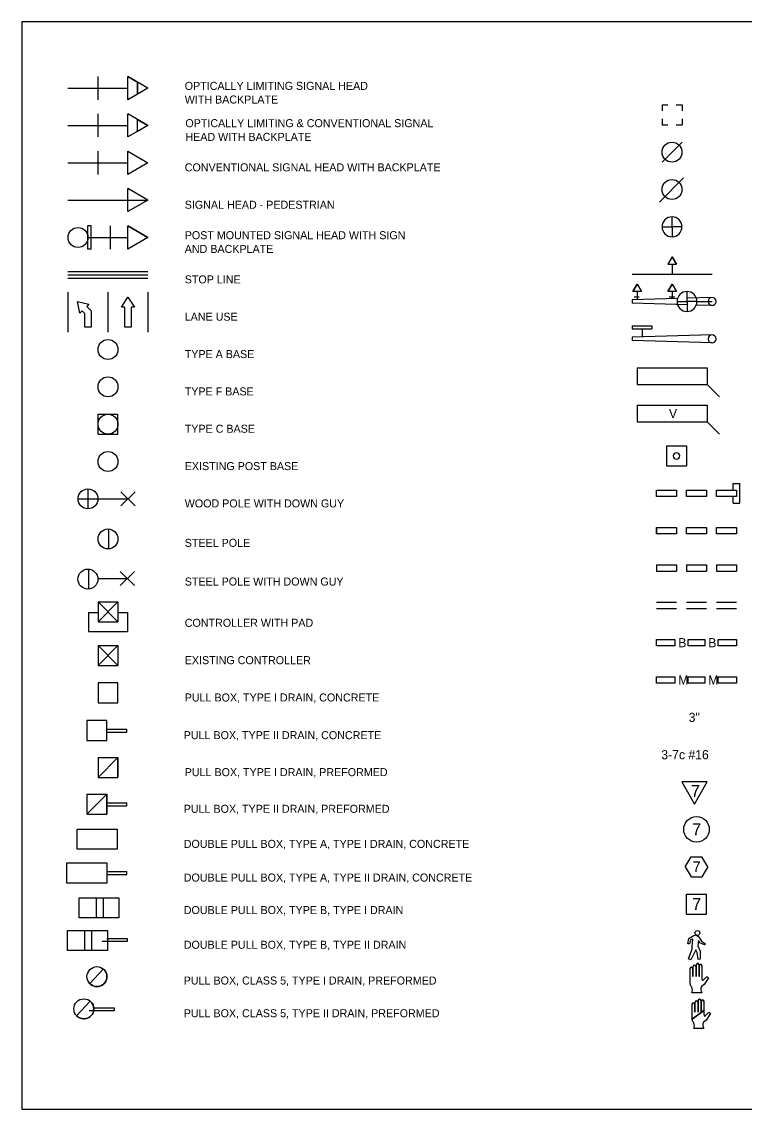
# Model space of a CAD drawing. Extents: x -439.1 to -407.9, y -458.1 to -437.7.
# Drawn here: x -439.11 to -425.57, y -458.05 to -437.68 of the extents above; entities that cross this region are included whole.
import ezdxf

# ---------------------------------------------------------------- set-up
doc = ezdxf.new("R2010")
doc.units = 0
doc.layers.add('Draft_Named_Boundary', color=7, linetype='Continuous')
doc.layers.add('Level 4', color=7, linetype='Continuous')

msp = doc.modelspace()

# ---------------------------------------------------------------- linework, layer by layer
at = {"layer": 'Draft_Named_Boundary'}
msp.add_lwpolyline([(-439.109, -458.051), (-407.859, -458.051), (-407.859, -437.676), (-439.109, -437.676)], close=True, dxfattribs=at)
at = {"layer": 'Level 4'}
for p, q in [((-437.68, -439.136), (-437.68, -438.703)), ((-437.119, -439.136), (-437.119, -438.703)), ((-436.744, -438.919), (-437.119, -438.703)), ((-436.938, -439.032), (-436.938, -438.807)), ((-438.243, -438.919), (-437.119, -438.919)), ((-436.744, -438.919), (-437.119, -439.136)), ((-427.112, -439.232), (-427.001, -439.232)), ((-427.112, -439.232), (-427.112, -439.343)), ((-426.848, -439.232), (-426.737, -439.232)), ((-426.737, -439.232), (-426.737, -439.343)), ((-437.68, -439.835), (-437.68, -439.403)), ((-436.744, -439.619), (-437.119, -439.403)), ((-437.119, -439.835), (-437.119, -439.403)), ((-438.243, -439.619), (-437.119, -439.619)), ((-436.744, -439.619), (-437.119, -439.835)), ((-436.938, -439.732), (-436.938, -439.506)), ((-427.112, -439.496), (-427.112, -439.607)), ((-427.112, -439.607), (-427.001, -439.607)), ((-426.848, -439.607), (-426.737, -439.607)), ((-426.737, -439.496), (-426.737, -439.607)), ((-426.737, -439.932), (-427.112, -440.307)), ((-437.68, -440.535), (-437.68, -440.102)), ((-437.119, -440.102), (-436.744, -440.319)), ((-437.119, -440.535), (-437.119, -440.102)), ((-438.243, -440.319), (-437.119, -440.319)), ((-436.744, -440.319), (-437.119, -440.535)), ((-426.708, -440.602), (-427.159, -441.053)), ((-436.744, -441.018), (-437.119, -440.802)), ((-437.119, -441.234), (-437.119, -440.802)), ((-438.243, -441.018), (-436.744, -441.018)), ((-436.744, -441.018), (-437.119, -441.234)), ((-437.868, -441.934), (-437.868, -441.501)), ((-437.808, -441.501), (-437.868, -441.501)), ((-437.808, -441.934), (-437.808, -441.501)), ((-437.444, -441.934), (-437.444, -441.501)), ((-436.744, -441.718), (-437.119, -441.501)), ((-437.119, -441.934), (-437.119, -441.501)), ((-427.112, -441.518), (-426.925, -441.518)), ((-426.925, -441.518), (-426.925, -441.331)), ((-426.737, -441.518), (-426.925, -441.518)), ((-426.925, -441.518), (-426.925, -441.706)), ((-426.737, -441.518), (-426.737, -441.518)), ((-437.868, -441.718), (-437.119, -441.718)), ((-436.744, -441.718), (-437.119, -441.934)), ((-437.808, -441.934), (-437.868, -441.934)), ((-426.925, -442.078), (-427.006, -442.218)), ((-426.925, -442.078), (-426.844, -442.218)), ((-427.006, -442.218), (-426.844, -442.218)), ((-426.925, -442.218), (-426.925, -442.405)), ((-438.243, -442.357), (-436.744, -442.357)), ((-438.243, -442.417), (-436.744, -442.417)), ((-438.243, -442.477), (-436.744, -442.477)), ((-427.674, -442.405), (-426.175, -442.405)), ((-438.243, -442.742), (-438.243, -443.492)), ((-437.493, -442.742), (-437.493, -443.492)), ((-436.744, -442.742), (-436.744, -443.492)), ((-427.581, -442.59), (-427.662, -442.73)), ((-427.581, -442.59), (-427.499, -442.73)), ((-427.581, -442.73), (-427.581, -442.884)), ((-426.925, -442.59), (-427.006, -442.73)), ((-426.925, -442.59), (-426.844, -442.73)), ((-426.925, -442.73), (-426.925, -442.865)), ((-426.643, -442.917), (-426.643, -442.73)), ((-438.019, -443.135), (-438.067, -442.918)), ((-438.067, -442.918), (-437.849, -442.965)), ((-437.238, -443.023), (-437.119, -442.836)), ((-437.128, -442.85), (-437.116, -442.839)), ((-437.119, -442.836), (-436.998, -443.023)), ((-426.823, -442.862), (-427.674, -442.887)), ((-427.674, -442.887), (-427.674, -442.948)), ((-426.643, -442.978), (-427.674, -442.948)), ((-427.633, -442.827), (-427.538, -442.827)), ((-426.976, -442.827), (-426.872, -442.827)), ((-426.831, -442.917), (-426.643, -442.917)), ((-426.456, -442.917), (-426.644, -442.917)), ((-426.644, -442.917), (-426.644, -443.105)), ((-426.175, -442.842), (-426.643, -442.857)), ((-426.456, -442.917), (-426.175, -442.917)), ((-437.977, -443.093), (-438.019, -443.135)), ((-437.928, -443.142), (-437.977, -443.093)), ((-437.928, -443.398), (-437.928, -443.142)), ((-437.849, -442.965), (-437.892, -443.008)), ((-437.892, -443.008), (-437.808, -443.092)), ((-437.808, -443.092), (-437.808, -443.398)), ((-437.179, -443.023), (-437.238, -443.023)), ((-437.179, -443.398), (-437.179, -443.023)), ((-436.998, -443.023), (-437.059, -443.023)), ((-437.059, -443.023), (-437.059, -443.398)), ((-426.175, -442.992), (-426.469, -442.984)), ((-437.808, -443.398), (-437.928, -443.398)), ((-437.059, -443.398), (-437.179, -443.398)), ((-427.674, -443.37), (-427.3, -443.37)), ((-427.674, -443.37), (-427.674, -443.429)), ((-427.674, -443.429), (-427.3, -443.429)), ((-426.175, -443.542), (-427.674, -443.587)), ((-427.487, -443.429), (-427.487, -443.581)), ((-427.3, -443.37), (-427.3, -443.429)), ((-427.674, -443.587), (-427.674, -443.647)), ((-426.175, -443.692), (-427.674, -443.647)), ((-427.581, -444.163), (-427.581, -444.47)), ((-427.581, -444.163), (-426.269, -444.163)), ((-426.269, -444.163), (-426.269, -444.47)), ((-427.581, -444.47), (-426.269, -444.47)), ((-426.269, -444.47), (-426.033, -444.705)), ((-427.581, -444.862), (-427.581, -445.169)), ((-427.581, -444.862), (-426.269, -444.862)), ((-426.269, -444.862), (-426.269, -445.169)), ((-437.68, -445.028), (-437.306, -445.028)), ((-437.68, -445.403), (-437.68, -445.028)), ((-437.306, -445.403), (-437.306, -445.028)), ((-427.581, -445.169), (-426.269, -445.169)), ((-426.269, -445.169), (-426.033, -445.405)), ((-437.68, -445.403), (-437.306, -445.403)), ((-427.028, -445.624), (-427.028, -445.998)), ((-427.028, -445.624), (-426.654, -445.624)), ((-426.654, -445.624), (-426.654, -445.998)), ((-427.028, -445.998), (-426.654, -445.998)), ((-425.777, -446.324), (-425.657, -446.324)), ((-425.777, -446.451), (-425.777, -446.324)), ((-425.657, -446.698), (-425.657, -446.324)), ((-438.055, -446.614), (-437.119, -446.614)), ((-437.868, -446.427), (-437.868, -446.802)), ((-436.986, -446.482), (-437.251, -446.747)), ((-437.251, -446.482), (-436.986, -446.747)), ((-427.216, -446.571), (-427.216, -446.451)), ((-427.216, -446.451), (-426.841, -446.451)), ((-426.841, -446.571), (-427.216, -446.571)), ((-426.841, -446.451), (-426.841, -446.571)), ((-426.654, -446.571), (-426.654, -446.451)), ((-426.654, -446.451), (-426.278, -446.451)), ((-426.278, -446.571), (-426.654, -446.571)), ((-426.278, -446.451), (-426.278, -446.571)), ((-426.091, -446.571), (-426.091, -446.451)), ((-426.091, -446.451), (-425.717, -446.451)), ((-425.717, -446.571), (-426.091, -446.571)), ((-425.777, -446.698), (-425.777, -446.571)), ((-425.717, -446.451), (-425.717, -446.571)), ((-425.777, -446.698), (-425.657, -446.698)), ((-437.481, -447.179), (-437.481, -447.553)), ((-427.216, -447.15), (-427.216, -447.271)), ((-427.216, -447.271), (-427.216, -447.15)), ((-427.216, -447.271), (-427.216, -447.15)), ((-427.216, -447.15), (-426.841, -447.15)), ((-426.841, -447.15), (-426.841, -447.271)), ((-426.654, -447.271), (-426.654, -447.15)), ((-426.654, -447.15), (-426.278, -447.15)), ((-426.278, -447.15), (-426.278, -447.271)), ((-426.091, -447.271), (-426.091, -447.15)), ((-426.091, -447.15), (-425.717, -447.15)), ((-425.717, -447.15), (-425.717, -447.271)), ((-426.841, -447.271), (-427.216, -447.271)), ((-426.278, -447.271), (-426.654, -447.271)), ((-425.717, -447.271), (-426.091, -447.271)), ((-437.856, -447.931), (-437.856, -448.305)), ((-436.997, -447.976), (-437.262, -448.241)), ((-437.262, -447.976), (-436.997, -448.241)), ((-427.216, -447.85), (-427.216, -447.97)), ((-427.216, -447.85), (-426.841, -447.85)), ((-427.216, -447.97), (-426.841, -447.97)), ((-426.841, -447.85), (-426.841, -447.97)), ((-426.654, -447.85), (-426.654, -447.97)), ((-426.654, -447.85), (-426.278, -447.85)), ((-426.654, -447.97), (-426.278, -447.97)), ((-426.278, -447.85), (-426.278, -447.97)), ((-426.091, -447.85), (-426.091, -447.97)), ((-426.091, -447.85), (-425.717, -447.85)), ((-426.091, -447.97), (-425.717, -447.97)), ((-425.717, -447.85), (-425.717, -447.97)), ((-437.682, -448.108), (-437.13, -448.108)), ((-437.68, -448.546), (-437.68, -448.92)), ((-437.68, -448.546), (-437.306, -448.546)), ((-437.68, -448.546), (-437.306, -448.92)), ((-437.306, -448.546), (-437.68, -448.92)), ((-437.306, -448.546), (-437.306, -448.92)), ((-427.216, -448.549), (-426.841, -448.549)), ((-426.654, -448.549), (-426.278, -448.549)), ((-426.091, -448.549), (-425.717, -448.549)), ((-437.859, -448.742), (-437.859, -449.099)), ((-437.859, -448.742), (-437.68, -448.742)), ((-437.306, -448.742), (-437.127, -448.742)), ((-437.127, -448.742), (-437.127, -449.099)), ((-427.216, -448.669), (-426.841, -448.669)), ((-426.654, -448.669), (-426.278, -448.669)), ((-426.091, -448.669), (-425.717, -448.669)), ((-437.68, -448.92), (-437.306, -448.92)), ((-437.859, -449.099), (-437.127, -449.099)), ((-427.216, -449.369), (-427.216, -449.25)), ((-427.216, -449.25), (-426.871, -449.25)), ((-426.871, -449.25), (-426.871, -449.369)), ((-426.623, -449.369), (-426.623, -449.25)), ((-426.623, -449.25), (-426.309, -449.25)), ((-426.309, -449.25), (-426.309, -449.369)), ((-426.062, -449.369), (-426.062, -449.25)), ((-426.062, -449.25), (-425.717, -449.25)), ((-425.717, -449.25), (-425.717, -449.369)), ((-437.306, -449.364), (-437.68, -449.738)), ((-437.68, -449.364), (-437.306, -449.364)), ((-437.68, -449.364), (-437.306, -449.738)), ((-437.68, -449.364), (-437.68, -449.738)), ((-437.306, -449.364), (-437.306, -449.738)), ((-426.871, -449.369), (-427.216, -449.369)), ((-426.309, -449.369), (-426.623, -449.369)), ((-425.717, -449.369), (-426.062, -449.369)), ((-437.68, -449.738), (-437.306, -449.738)), ((-437.306, -450.063), (-437.68, -450.063)), ((-437.68, -450.063), (-437.68, -450.438)), ((-437.306, -450.438), (-437.306, -450.063)), ((-427.216, -450.068), (-427.216, -449.949)), ((-427.216, -449.949), (-426.871, -449.949)), ((-426.871, -450.068), (-427.216, -450.068)), ((-426.871, -449.949), (-426.871, -450.068)), ((-426.623, -450.068), (-426.623, -449.949)), ((-426.623, -449.949), (-426.309, -449.949)), ((-426.309, -450.068), (-426.623, -450.068)), ((-426.309, -449.949), (-426.309, -450.068)), ((-426.062, -450.068), (-426.062, -449.949)), ((-426.062, -449.949), (-425.717, -449.949)), ((-425.717, -450.068), (-426.062, -450.068)), ((-425.717, -449.949), (-425.717, -450.068)), ((-437.68, -450.438), (-437.306, -450.438)), ((-437.512, -450.769), (-437.887, -450.769)), ((-437.887, -450.769), (-437.887, -451.144)), ((-437.512, -451.144), (-437.512, -450.769)), ((-437.512, -450.927), (-437.137, -450.927)), ((-437.512, -450.986), (-437.137, -450.986)), ((-437.137, -450.986), (-437.137, -450.927)), ((-437.887, -451.144), (-437.512, -451.144)), ((-437.68, -451.463), (-437.68, -451.837)), ((-437.68, -451.463), (-437.306, -451.463)), ((-437.306, -451.463), (-437.68, -451.837)), ((-437.306, -451.463), (-437.306, -451.837)), ((-437.68, -451.837), (-437.306, -451.837)), ((-426.264, -451.919), (-426.743, -451.919)), ((-426.743, -451.919), (-426.504, -452.333)), ((-426.504, -452.333), (-426.264, -451.919)), ((-437.887, -452.149), (-437.887, -452.524)), ((-437.887, -452.149), (-437.512, -452.149)), ((-437.887, -452.524), (-437.512, -452.149)), ((-437.512, -452.149), (-437.512, -452.524)), ((-437.512, -452.307), (-437.137, -452.307)), ((-437.137, -452.367), (-437.137, -452.307)), ((-437.887, -452.524), (-437.512, -452.524)), ((-437.512, -452.367), (-437.137, -452.367)), ((-426.677, -453.507), (-426.569, -453.319)), ((-426.569, -453.319), (-426.364, -453.319)), ((-426.256, -453.507), (-426.364, -453.319)), ((-426.677, -453.507), (-426.569, -453.694)), ((-426.256, -453.507), (-426.364, -453.694)), ((-437.512, -453.595), (-437.137, -453.595)), ((-437.512, -453.655), (-437.137, -453.655)), ((-437.137, -453.655), (-437.137, -453.595)), ((-426.569, -453.694), (-426.364, -453.694)), ((-438.036, -454.092), (-437.287, -454.092)), ((-426.654, -454.019), (-426.278, -454.019)), ((-426.654, -454.394), (-426.654, -454.019)), ((-426.278, -454.394), (-426.278, -454.019)), ((-437.287, -454.467), (-438.036, -454.467)), ((-426.654, -454.394), (-426.278, -454.394)), ((-438.251, -454.7), (-437.502, -454.7)), ((-426.631, -454.95), (-426.612, -454.854)), ((-426.6, -454.952), (-426.631, -454.95)), ((-426.612, -454.854), (-426.526, -454.804)), ((-426.578, -454.874), (-426.6, -454.952)), ((-426.536, -454.862), (-426.578, -454.874)), ((-426.55, -455.001), (-426.536, -454.862)), ((-426.526, -454.804), (-426.49, -454.792)), ((-426.49, -454.792), (-426.481, -454.785)), ((-426.49, -454.792), (-426.49, -454.792)), ((-426.481, -454.785), (-426.465, -454.794)), ((-426.465, -454.794), (-426.451, -454.795)), ((-426.451, -454.795), (-426.444, -454.806)), ((-426.444, -454.806), (-426.421, -454.823)), ((-426.431, -454.891), (-426.44, -454.99)), ((-426.404, -454.93), (-426.431, -454.891)), ((-426.421, -454.823), (-426.375, -454.903)), ((-426.314, -454.972), (-426.404, -454.93)), ((-426.375, -454.903), (-426.299, -454.954)), ((-426.299, -454.954), (-426.314, -454.972)), ((-437.502, -455.075), (-438.251, -455.075)), ((-426.613, -455.235), (-426.545, -455.054)), ((-426.48, -455.064), (-426.572, -455.25)), ((-426.545, -455.054), (-426.55, -455.001)), ((-426.452, -455.117), (-426.48, -455.064)), ((-426.437, -455.244), (-426.452, -455.117)), ((-426.44, -454.99), (-426.399, -455.088)), ((-426.399, -455.088), (-426.396, -455.241)), ((-426.572, -455.25), (-426.613, -455.235)), ((-426.527, -455.551), (-426.527, -455.378)), ((-426.481, -455.378), (-426.481, -455.551)), ((-426.469, -455.551), (-426.469, -455.343)), ((-426.396, -455.241), (-426.437, -455.244)), ((-426.423, -455.343), (-426.423, -455.551)), ((-426.411, -455.551), (-426.411, -455.361)), ((-426.365, -455.361), (-426.365, -455.602)), ((-437.579, -455.423), (-437.836, -455.696)), ((-437.579, -455.423), (-437.836, -455.696)), ((-426.585, -455.705), (-426.585, -455.413)), ((-426.539, -455.413), (-426.539, -455.551)), ((-426.248, -455.583), (-426.24, -455.591)), ((-426.36, -455.626), (-426.358, -455.63)), ((-426.34, -455.633), (-426.297, -455.586)), ((-426.365, -455.868), (-426.556, -455.868)), ((-437.824, -456.027), (-438.081, -456.299)), ((-437.824, -456.027), (-438.081, -456.299)), ((-426.547, -456.374), (-426.547, -456.081)), ((-426.501, -456.081), (-426.501, -456.22)), ((-426.489, -456.22), (-426.489, -456.047)), ((-426.443, -456.047), (-426.443, -456.22)), ((-426.431, -456.22), (-426.431, -456.012)), ((-426.385, -456.012), (-426.385, -456.22)), ((-426.373, -456.22), (-426.373, -456.029)), ((-426.327, -456.029), (-426.327, -456.201)), ((-426.547, -456.363), (-426.327, -456.201)), ((-426.327, -456.201), (-426.327, -456.271)), ((-426.322, -456.295), (-426.32, -456.298)), ((-426.302, -456.302), (-426.259, -456.254)), ((-426.21, -456.252), (-426.202, -456.26)), ((-426.327, -456.537), (-426.518, -456.537))]:
    msp.add_line(p, q, dxfattribs=at)
for points in [[(-437.119, -438.703), (-436.938, -438.807), (-436.938, -439.032), (-437.119, -439.136)], [(-436.938, -439.506), (-436.744, -439.619), (-436.938, -439.732)], [(-436.744, -441.018), (-437.119, -441.234), (-437.119, -441.018)], [(-437.119, -441.501), (-436.744, -441.718), (-437.119, -441.934)], [(-426.925, -442.078), (-427.006, -442.218), (-426.844, -442.218)], [(-427.662, -442.73), (-427.581, -442.59), (-427.499, -442.73)], [(-427.006, -442.73), (-426.925, -442.59), (-426.844, -442.73)], [(-437.306, -451.463), (-437.68, -451.837), (-437.306, -451.837)], [(-437.512, -452.149), (-437.887, -452.524), (-437.512, -452.524)], [(-438.073, -452.805), (-437.324, -452.805), (-437.324, -453.181), (-438.073, -453.181)], [(-438.262, -453.437), (-437.512, -453.437), (-437.512, -453.812), (-438.262, -453.812)], [(-426.547, -456.363), (-426.547, -456.081), (-426.542, -456.065), (-426.532, -456.057), (-426.518, -456.057), (-426.508, -456.062), (-426.501, -456.081), (-426.501, -456.22), (-426.497, -456.225), (-426.493, -456.225), (-426.49, -456.225), (-426.49, -456.22), (-426.489, -456.22), (-426.489, -456.047), (-426.489, -456.047), (-426.483, -456.03), (-426.466, -456.02), (-426.451, -456.027), (-426.443, -456.047), (-426.443, -456.22), (-426.439, -456.225), (-426.435, -456.225), (-426.432, -456.225), (-426.431, -456.22), (-426.431, -456.012), (-426.431, -456.003), (-426.42, -455.99), (-426.407, -455.986), (-426.392, -455.992), (-426.385, -456.012), (-426.385, -456.22), (-426.385, -456.227), (-426.379, -456.227), (-426.374, -456.227), (-426.374, -456.218), (-426.373, -456.22), (-426.373, -456.029), (-426.367, -456.013), (-426.35, -456.003), (-426.336, -456.01), (-426.327, -456.029), (-426.327, -456.201)]]:
    msp.add_lwpolyline(points, close=True, dxfattribs=at)
for points in [[(-437.717, -454.467), (-438.036, -454.467), (-438.036, -454.092), (-437.717, -454.092)], [(-437.717, -454.092), (-437.717, -454.467)], [(-437.578, -454.467), (-437.578, -454.092)], [(-437.578, -454.092), (-437.287, -454.092), (-437.287, -454.467), (-437.578, -454.467)], [(-437.932, -455.075), (-438.251, -455.075), (-438.251, -454.7), (-437.932, -454.7)], [(-437.932, -454.7), (-437.932, -455.075)], [(-437.793, -455.075), (-437.793, -454.7)], [(-437.793, -454.7), (-437.502, -454.7), (-437.502, -455.075), (-437.793, -455.075)], [(-437.515, -454.849), (-437.136, -454.849), (-437.136, -454.906), (-437.604, -454.906)], [(-426.24, -455.591), (-426.325, -455.711), (-426.371, -455.753)], [(-437.758, -456.15), (-437.378, -456.15), (-437.378, -456.207), (-437.846, -456.207)], [(-426.202, -456.26), (-426.287, -456.379), (-426.333, -456.421)]]:
    msp.add_lwpolyline(points, dxfattribs=at)
for centre, radius in [((-426.925, -440.119), 0.187), ((-426.925, -440.819), 0.187), ((-438.055, -441.718), 0.187), ((-437.493, -443.816), 0.187), ((-437.493, -444.516), 0.187), ((-437.493, -445.216), 0.187), ((-437.493, -445.915), 0.187), ((-437.868, -446.615), 0.187), ((-437.493, -447.366), 0.187), ((-437.869, -448.118), 0.187), ((-426.466, -452.807), 0.24), ((-426.449, -454.747), 0.0455), ((-437.7, -455.566), 0.187), ((-437.946, -456.169), 0.187)]:
    msp.add_circle(centre, radius, dxfattribs=at)
for centre, radius, start, end in [((-426.925, -441.518), 0.187, 89.9559, 179.9354), ((-426.925, -441.518), 0.187, 179.9366, 270.0444), ((-426.925, -441.518), 0.187, 0.0646, 89.9559), ((-426.925, -441.518), 0.187, 270.0444, 0.0635), ((-426.644, -442.917), 0.187, 89.9177, 180.0052), ((-426.644, -442.917), 0.187, 359.9996, 90.0025), ((-426.644, -442.917), 0.187, 180.0004, 269.9975), ((-426.644, -442.917), 0.187, 269.9975, 359.9996), ((-426.175, -442.917), 0.0751, 0, 180), ((-426.175, -442.917), 0.0751, 180, 0), ((-426.175, -443.617), 0.0751, 0, 180), ((-426.175, -443.617), 0.0751, 180, 0), ((-426.841, -445.811), 0.06, 0, 180), ((-426.841, -445.811), 0.06, 180, 0), ((-437.7, -455.566), 0.187, 223.8566, 0), ((-437.7, -455.566), 0.187, 0, 49.5536), ((-437.946, -456.169), 0.187, 223.8566, 0), ((-437.946, -456.169), 0.187, 0, 49.5536)]:
    msp.add_arc(centre, radius, start, end, dxfattribs=at)
for centre, major_axis, start_param, end_param in [((-426.504, -455.378), (0, 0.0266), 4.712442, 7.853971), ((-426.446, -455.343), (0, 0.0266), 4.712442, 7.853967), ((-426.388, -455.361), (0, 0.0266), 4.712336, 7.853967), ((-426.562, -455.413), (0, 0.0266), 4.712442, 7.853966), ((-426.533, -455.551), (0, 0.00665), 1.570808, 4.712442), ((-426.475, -455.551), (0, 0.00665), 1.570796, 4.712382), ((-426.417, -455.551), (0, 0.00665), 1.570796, 4.712387), ((-426.271, -455.616), (0, 0.0425), 5.596656, 7.058644), ((-426.52, -455.697), (0, -0.0751), 4.819258, 5.643493), ((-426.573, -455.779), (0, 0.0266), 5.196586, 5.643493), ((-426.651, -455.813), (0, 0.123), 4.24666, 5.108756), ((-426.307, -455.806), (0, 0.0908), 0.939503, 2.323396), ((-426.318, -455.602), (0, -0.0532), 4.712389, 5.188198), ((-426.348, -455.624), (0, -0.0133), 5.188193, 7.058644), ((-426.408, -456.012), (0, 0.0266), 4.712442, 7.853967), ((-426.524, -456.081), (0, 0.0266), 4.712442, 7.853966), ((-426.466, -456.047), (0, 0.0266), 4.712442, 7.853971), ((-426.35, -456.029), (0, 0.0266), 4.712336, 7.853967), ((-426.482, -456.366), (0, -0.0751), 4.819258, 5.643493), ((-426.495, -456.22), (0, 0.00665), 1.570808, 4.712442), ((-426.437, -456.22), (0, 0.00665), 1.570796, 4.712382), ((-426.379, -456.22), (0, 0.00665), 1.570796, 4.712387), ((-426.28, -456.271), (0, -0.0532), 4.712389, 5.188198), ((-426.31, -456.292), (0, -0.0133), 5.188193, 7.058644), ((-426.233, -456.285), (0, 0.0425), 5.596656, 7.058644), ((-426.535, -456.447), (0, 0.0266), 5.196586, 5.643493), ((-426.613, -456.482), (0, 0.123), 4.24666, 5.108756), ((-426.269, -456.475), (0, 0.0908), 0.939503, 2.323396)]:
    msp.add_ellipse(centre, major_axis=major_axis, ratio=0.872945, start_param=start_param, end_param=end_param, dxfattribs=at)

# ---------------------------------------------------------------- texts
for s, height, p in [('OPTICALLY LIMITING SIGNAL HEAD', 0.15, (-436.055, -438.952)), ('WITH BACKPLATE', 0.15, (-436.055, -439.208)), ('OPTICALLY LIMITING & CONVENTIONAL SIGNAL', 0.15, (-436.043, -439.651)), ('HEAD WITH BACKPLATE', 0.15, (-436.043, -439.908)), ('CONVENTIONAL SIGNAL HEAD WITH BACKPLATE', 0.15, (-436.055, -440.479)), ('SIGNAL HEAD - PEDESTRIAN', 0.15, (-436.055, -441.179)), ('POST MOUNTED SIGNAL HEAD WITH SIGN', 0.15, (-436.055, -441.75)), ('AND BACKPLATE', 0.15, (-436.055, -442.007)), ('STOP LINE', 0.15, (-436.055, -442.578)), ('LANE USE', 0.15, (-436.055, -443.277)), ('TYPE A BASE', 0.15, (-436.055, -443.977)), ('TYPE F BASE', 0.15, (-436.055, -444.677)), ('V', 0.171, (-426.982, -445.101)), ('TYPE C BASE', 0.15, (-436.055, -445.376)), ('EXISTING POST BASE', 0.15, (-436.055, -446.076)), ('WOOD POLE WITH DOWN GUY', 0.15, (-436.055, -446.775)), ('STEEL POLE', 0.15, (-436.055, -447.514)), ('STEEL POLE WITH DOWN GUY', 0.15, (-436.055, -448.239)), ('CONTROLLER WITH PAD', 0.15, (-436.055, -449.012)), ('B', 0.171, (-426.808, -449.395)), ('B', 0.171, (-426.246, -449.395)), ('EXISTING CONTROLLER', 0.15, (-436.055, -449.712)), ('M', 0.171, (-426.808, -450.094)), ('M', 0.171, (-426.246, -450.094)), ('PULL BOX, TYPE I DRAIN, CONCRETE', 0.15, (-436.055, -450.411)), ('3"', 0.171, (-426.613, -450.794)), ('PULL BOX, TYPE II DRAIN, CONCRETE', 0.15, (-436.074, -451.117)), ('3-7c #16', 0.171, (-427.126, -451.493)), ('PULL BOX, TYPE I DRAIN, PREFORMED', 0.15, (-436.055, -451.81)), ('7', 0.228, (-426.57, -452.202)), ('PULL BOX, TYPE II DRAIN, PREFORMED', 0.15, (-436.074, -452.497)), ('7', 0.228, (-426.548, -452.921)), ('DOUBLE PULL BOX, TYPE A, TYPE I DRAIN, CONCRETE', 0.15, (-436.074, -453.154)), ('7', 0.199, (-426.537, -453.606)), ('DOUBLE PULL BOX, TYPE A, TYPE II DRAIN, CONCRETE', 0.15, (-436.074, -453.785)), ('7', 0.228, (-426.548, -454.32)), ('DOUBLE PULL BOX, TYPE B, TYPE I DRAIN', 0.15, (-436.073, -454.394)), ('DOUBLE PULL BOX, TYPE B, TYPE II DRAIN', 0.15, (-436.073, -455.044)), ('PULL BOX, CLASS 5, TYPE I DRAIN, PREFORMED', 0.15, (-436.074, -455.714)), ('PULL BOX, CLASS 5, TYPE II DRAIN, PREFORMED', 0.15, (-436.074, -456.327))]:
    msp.add_text(s, height=height, dxfattribs=at).set_placement(p)

doc.saveas('drawing.dxf')
